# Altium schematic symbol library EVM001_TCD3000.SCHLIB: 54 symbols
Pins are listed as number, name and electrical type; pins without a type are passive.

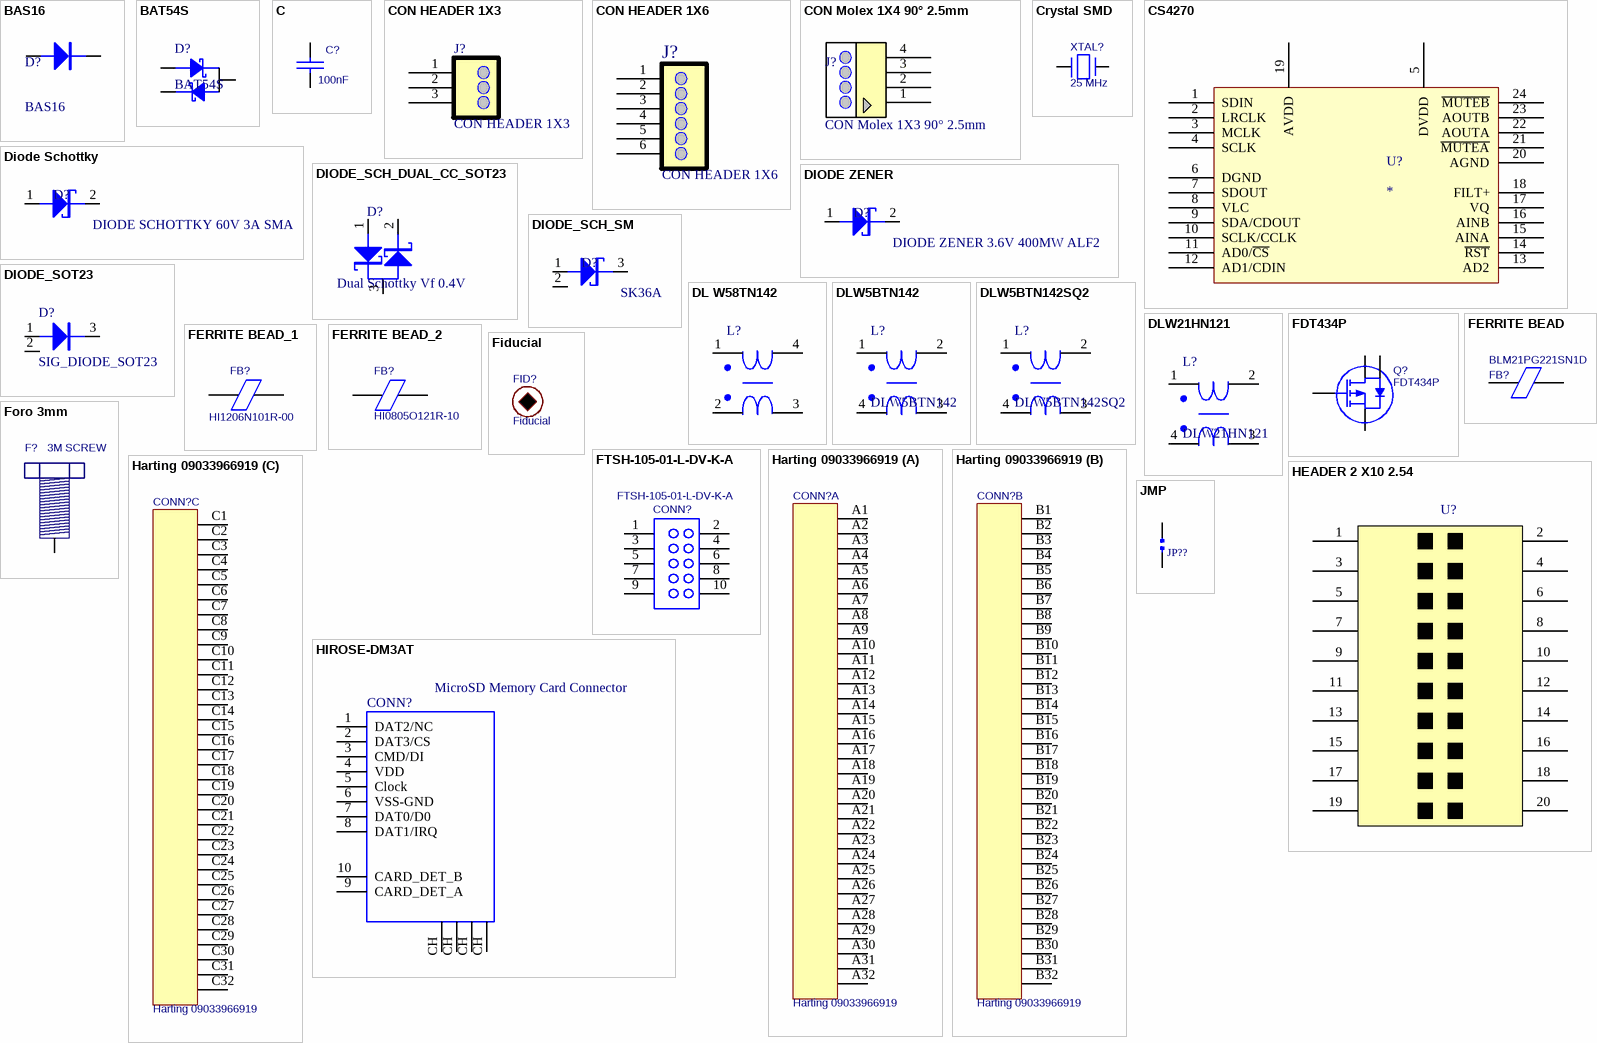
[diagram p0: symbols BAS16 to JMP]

## BAS16
designator D?
Diode
footprint SOT23
pins: 1 A, 3 K

## BAT54S
designator D?
Schottky Diodes; Manufacturer: FAIRCHILD
footprint SOT23
pins: 1, 2, 3

## C
designator C?, comment 100nF
Capacitor SMD Ceramic X7R
footprint 0402_C (Capacità SMD 0402)
footprint 0603_c (Capacità SMD 0603)
footprint 0805_C (Capacità SMD 0805)
pins: 1, 2

## CON HEADER 1X3
designator J?
Header 1 x 3
footprint HDR1X3
pins: 1, 2, 3

## CON HEADER 1X6
designator J?
Header 1 x 6
footprint HDR1X6
pins: 1, 2, 3, 4, 5, 6
2 alternate drawings of the same symbol

## CON Molex 1X4 90° 2.5mm
designator J?, comment CON Molex 1X3 90° 2.5mm
Part Field 1: Molex Inc 0894000420
footprint Molex Spox 4pin (CONN HEADER 4POS 2MM VERT T/H)
pins: 1, 2, 3, 4

## Crystal SMD
designator XTAL?, comment 25 MHz
25MHz +/-30ppm 18pF; Manufacturer: TXC; Manufacturer Code: 7A-25.000MAAJ-T
footprint TXC 7A SERIES
pins: 1, 2

## CS4270
designator U?
CODEC; Part Field 1: DK CS4270-CZZR-ND
footprint TSOP65P640-24AN (TSOP, 24-Leads, Body 7.8x4.4mm, Pitch 0.65mm, IPC Medium Density)
pins: 1 SDIN, 2 LRCLK, 3 MCLK, 4 SCLK, 5 DVDD (power), 6 DGND (power), 7 SDOUT, 8 VLC, 9 SDA/CDOUT, 10 SCLK/CCLK, 11 AD0/~{CS}, 12 AD1/CDIN, 13 AD2, 14 ~{RST}, 15 AINA, 16 AINB, 17 VQ, 18 FILT+, 19 AVDD (power), 20 AGND (power), 21 ~{MUTEA}, 22 AOUTA, 23 AOUTB, 24 ~{MUTEB}

## Diode Schottky
designator D?, comment DIODE SCHOTTKY 60V 3A SMA
Part field 1: Micro Commercial Co SK36A-TP
footprint DIODE_SMA
pins: 1, 2

## DIODE ZENER
designator D?, comment DIODE ZENER 3.6V 400MW ALF2
Part field 1: NXP Semiconductors
footprint DIODE_SMA
pins: 1, 2

## DIODE_SCH_DUAL_CC_SOT23
designator D?, comment Dual Schottky Vf 0.4V
BAT54S; Part field 1: Fairchild Semiconductor  BAT54S
footprint SOT23-3N
pins: 1, 2 NC, 3

## DIODE_SCH_SM
designator D?, comment SK36A
Diode Schottky
footprint SOT23-3N
pins: 1, 2 NC, 3

## DIODE_SOT23
designator D?, comment SIG_DIODE_SOT23
Part Field 1: Zetex BAS21
footprint SOT23CC
footprint SOT23
pins: 1, 2 NC, 3
2 alternate drawings of the same symbol

## DL W58TN142
designator L?
TRASF
footprint CM3322
footprint WE-SL2 (SMD Common Mode Line Filter)
pins: 1, 2, 3, 4

## DLW5BTN142
designator L?
CHOKE COMMON MODE 1400 OHM 2020
footprint CM3322
footprint WE-SL2 (SMD Common Mode Line Filter)
pins: 1, 2, 3, 4

## DLW5BTN142SQ2
designator L?
CHOKE COMMON MODE 1400 OHM 2020
footprint CM3322
footprint WE-SL2 (SMD Common Mode Line Filter)
pins: 1, 2, 3, 4

## DLW21HN121
designator L?
CHOKE COMMON MODE 120 OHM 0805
footprint CM3322
footprint WE-SL2 (SMD Common Mode Line Filter)
pins: 1, 2, 3, 4

## FDT434P
designator Q?
P-Channel 2.5V Specified PowerTrench MOSFET; Manufacturer: Fairchild
footprint SOT-223
pins: 1 G, 2 D, 3 S, 4 D

## FERRITE BEAD
designator FB?, comment BLM21PG221SN1D
Ferrite Bead 3A 220Ohm; Manufacturer: Murata
footprint 0805_L (Ferrite SMD 0805)
pins: 1, 2

## FERRITE BEAD_1
designator FB?, comment HI1206N101R-00
Ferrite Bead 3A 100Ohm; Manufacturer: Laird-Signal Integrity Products
footprint 1206_l
pins: 1, 2

## FERRITE BEAD_2
designator FB?, comment HI0805O121R-10
Ferrite Bead 3.5A 120Ohm; Manufacturer: Laird-Signal Integrity Products
footprint 1206_l
footprint 0805_L (Ferrite SMD 0805)
pins: 1, 2

## Fiducial
designator FID?  (no BOM)
footprint FIDUCIAL 3MM R

## Foro 3mm
designator F?, comment 3M SCREW  (no BOM)
footprint SCREW M3 (Vite 3mm)
pins: 1

## FTSH-105-01-L-DV-K-A
designator CONN?
.050'' Micro Terminal Strip; Manufacturer: Samtec
footprint FTSH-105-01-L-DV-K-A (SMD Micro Header 1.27mm Pitch)
pins: 1, 2, 3, 4, 5, 6, 7, 8, 9, 10

## Harting 09033966919
designator CONN?
VME Male 96 Pin
footprint Harting 09033966919 (VME male Connecotr)
part A pins: A1, A2, A3, A4, A5, A6, A7, A8, A9, A10, A11, A12, A13, A14, A15, A16, A17, A18, A19, A20, A21, A22, A23, A24, A25, A26, A27, A28, A29, A30, A31, A32
part B pins: B1, B2, B3, B4, B5, B6, B7, B8, B9, B10, B11, B12, B13, B14, B15, B16, B17, B18, B19, B20, B21, B22, B23, B24, B25, B26, B27, B28, B29, B30, B31, B32
part C pins: C1, C2, C3, C4, C5, C6, C7, C8, C9, C10, C11, C12, C13, C14, C15, C16, C17, C18, C19, C20, C21, C22, C23, C24, C25, C26, C27, C28, C29, C30, C31, C32

## HEADER 2 X10 2.54
designator U?  (value not drawn)
HEADER 2X10
footprint IDC2.54-V64C 5 X 81.28 (Connector; IDC, PCB Transition - 2 Rows, Thru-Hole; 64 Position; Vertical; Pitch 2.54 mm; Body 86.58 x 6.1 x 7.45 mm (LxWxH), Kinked Contacts)
pins: 1, 2, 3, 4, 5, 6, 7, 8, 9, 10, 11, 12, 13, 14, 15, 16, 17, 18, 19, 20

## HIROSE-DM3AT
designator CONN?, comment MicroSD Memory Card Connector
CONN MICRO SD R/A PUSH-PUSH SMD; Manufacturer: Hirose Electric Co Ltd; Manufacturer Code: DM3AT-SF-PEJM5
footprint DM3AT (Footprint not found)
pins: 1 DAT2/NC, 2 DAT3/CS, 3 CMD/DI, 4 VDD, 5 Clock, 6 VSS-GND, 7 DAT0/D0, 8 DAT1/IRQ, 9 CARD_DET_A, 10 CARD_DET_B, CH, CH, CH, CH

## JMP
designator JP??, comment JUMP 0.1"  (value not drawn)
footprint HDR1X2
footprint HDR1X2
pins: 1, 2

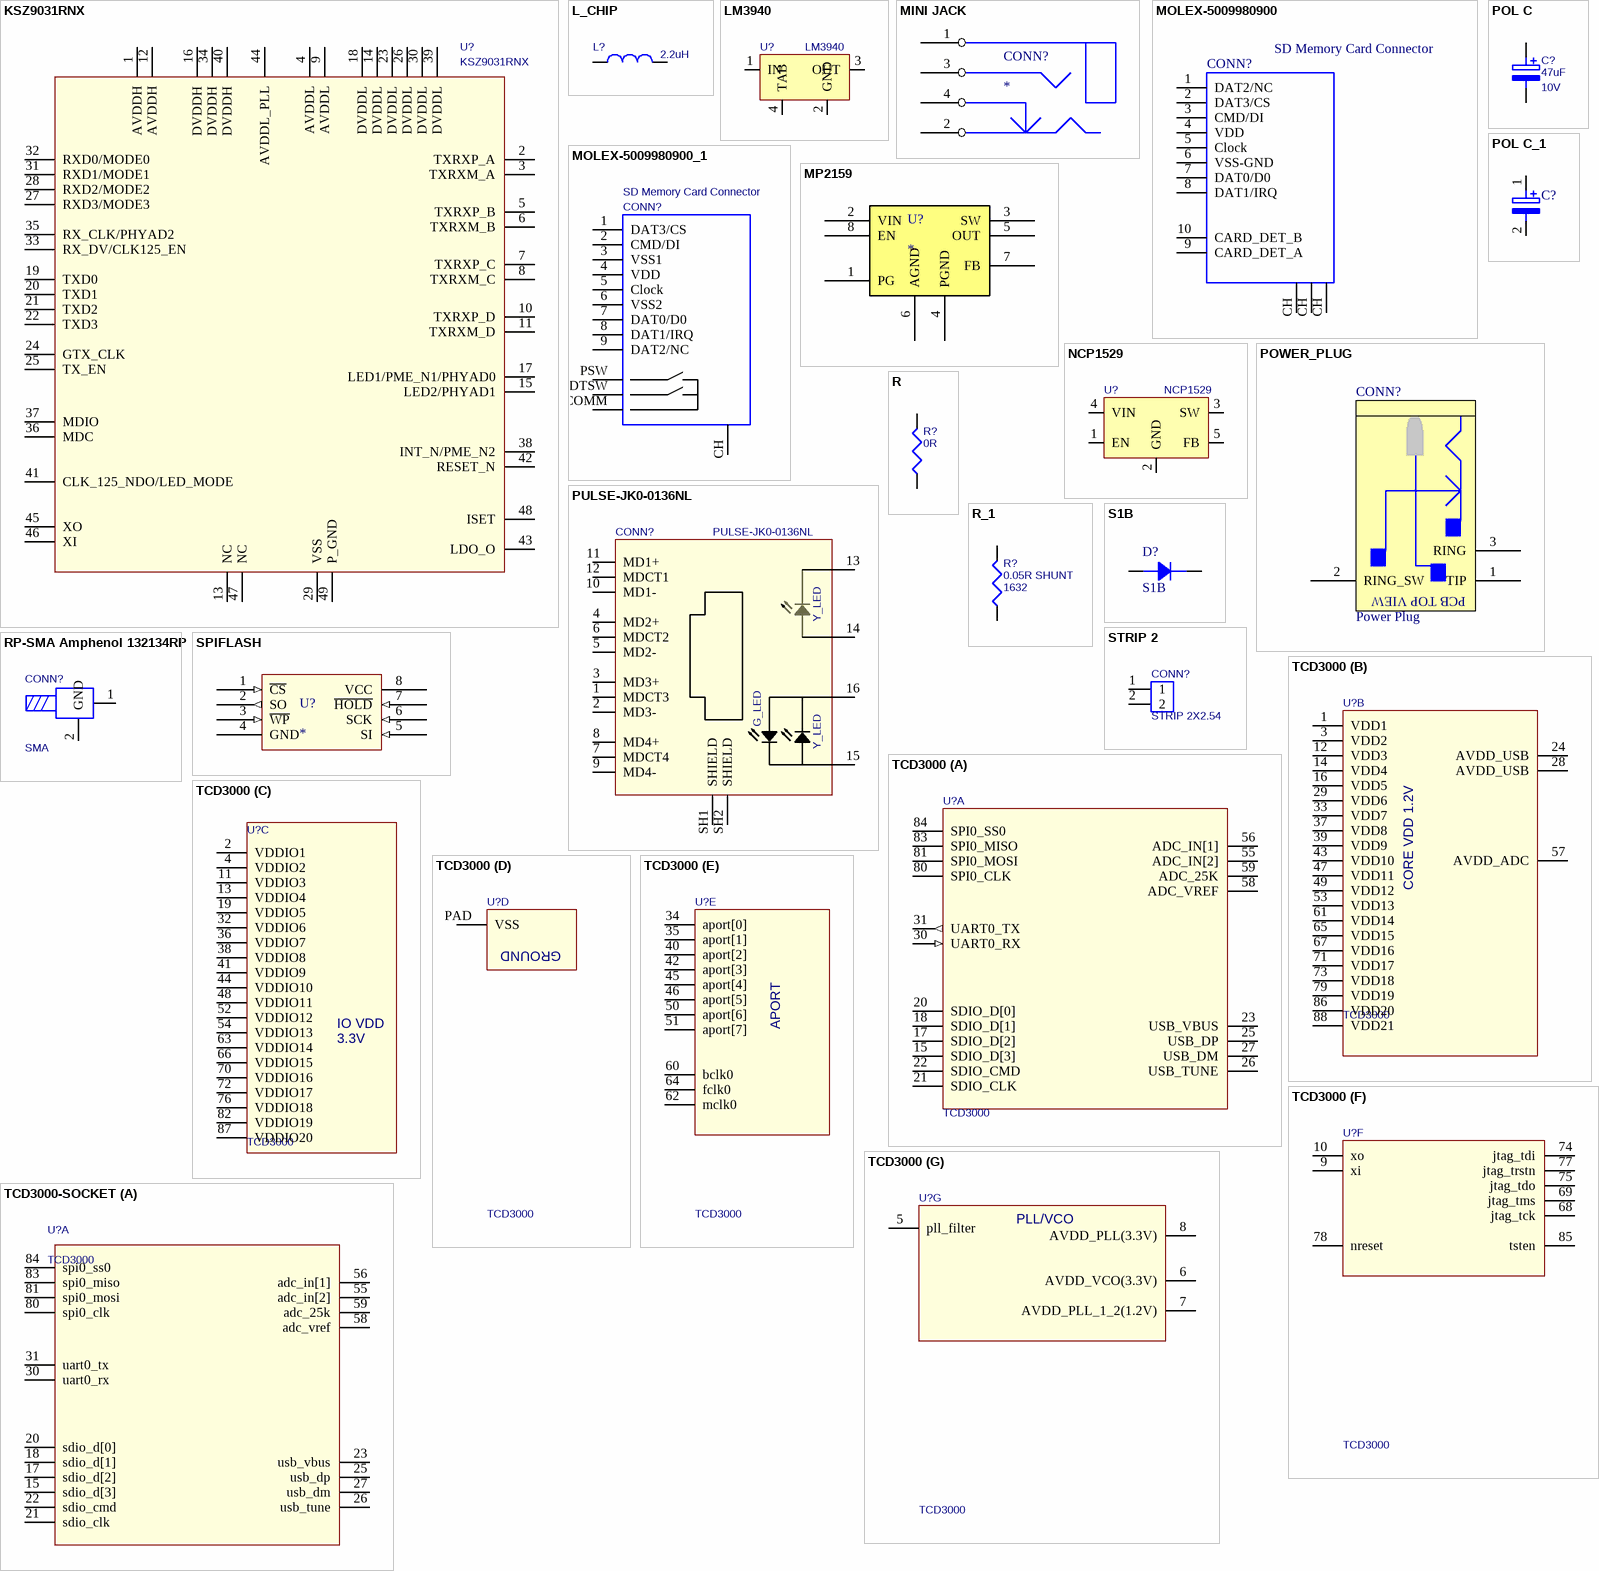
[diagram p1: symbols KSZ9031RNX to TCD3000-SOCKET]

## KSZ9031RNX
designator U?
Gigabit Ethernet Transceiver with RGMII Support; Manufacturer: Micrel; Manufacturer Code: 48-QFN
footprint MICREL-QFN-48
pins: 1 AVDDH, 2 TXRXP_A, 3 TXRXM_A, 4 AVDDL, 5 TXRXP_B, 6 TXRXM_B, 7 TXRXP_C, 8 TXRXM_C, 9 AVDDL, 10 TXRXP_D, 11 TXRXM_D, 12 AVDDH, 13 NC, 14 DVDDL, 15 LED2/PHYAD1, 16 DVDDH, 17 LED1/PME_N1/PHYAD0, 18 DVDDL, 19 TXD0, 20 TXD1, 21 TXD2, 22 TXD3, 23 DVDDL, 24 GTX_CLK, 25 TX_EN, 26 DVDDL, 27 RXD3/MODE3, 28 RXD2/MODE2, 29 VSS, 30 DVDDL, 31 RXD1/MODE1, 32 RXD0/MODE0, 33 RX_DV/CLK125_EN, 34 DVDDH, 35 RX_CLK/PHYAD2, 36 MDC, 37 MDIO, 38 INT_N/PME_N2, 39 DVDDL, 40 DVDDH, 41 CLK_125_NDO/LED_MODE, 42 RESET_N, 43 LDO_O, 44 AVDDL_PLL, 45 XO, 46 XI, 47 NC, 48 ISET, 49 P_GND

## L_CHIP
designator L?, comment 2.2uH
Chip Inductor SMD, 2.2uH, 1.3A, 80mOhm; Manufacturer: Murata; Manufacturer Code: LQM2HPN2R2MG0L
footprint Taiyo Yuden Power-Ind NR Series
footprint 1208_L
pins: 1, 2

## LM3940
designator U?
1A Low Dropout Regulator for 5V to 3.3V Conversion; Manufacturer: Texas Instruments; Manufacturer Code: LM3940IMP-3.3
footprint SOT-223
pins: 1 IN, 2 GND, 3 OUT, 4 TAB

## MINI JACK
designator CONN?
footprint SJ1_3514_SMT
pins: 1, 2, 3, 4

## MOLEX-5009980900
designator CONN?, comment SD Memory Card Connector
SD Memory Card Connector, 2.50mm Pitch, Shielded, Top Mount, Push-Push Ejector; Manufacturer: Molex; Manufacturer Code: 5009980900
footprint MOLEX - 5009980900 (2.50mm (.098") Pitch SD Memory Card Connector, Shielded, Top Mount, Push-Push Ejector)
pins: 1 DAT2/NC, 2 DAT3/CS, 3 CMD/DI, 4 VDD, 5 Clock, 6 VSS-GND, 7 DAT0/D0, 8 DAT1/IRQ, 9 CARD_DET_A, 10 CARD_DET_B, CH, CH, CH

## MOLEX-5009980900_1
designator CONN?, comment SD Memory Card Connector
SD Memory Card Connector, 2.50mm Pitch, Shielded, Top Mount, Push-Push Ejector; Manufacturer: Molex; Manufacturer Code: 5009980900
footprint MOLEX - 5009980900 (2.50mm (.098") Pitch SD Memory Card Connector, Shielded, Top Mount, Push-Push Ejector)
pins: 1 DAT3/CS, 2 CMD/DI, 3 VSS1, 4 VDD, 5 Clock, 6 VSS2, 7 DAT0/D0, 8 DAT1/IRQ, 9 DAT2/NC, CH, COMM, DTSW, PSW

## MP2159
designator U?
Voltage Regulators - Switching Regulators 1A, 6V, 1.5MHz COT Sync Step Dwn Swtchr; Part field 1: Mouser  946-MP2159GJP
pins: 1 PG, 2 VIN (power), 3 SW, 4 PGND (power), 5 OUT, 6 AGND (power), 7 FB, 8 EN

## NCP1529
designator U?
1.7MHz, 1A, High Efficiency, Low Ripple, Adjustable Output Voltage Step-down Converter; Manufacturer: On Semiconductor
footprint TSOP-5
pins: 1 EN, 2 GND, 3 SW, 4 VIN, 5 FB

## POL C
designator C?, comment 47uF  VOLT: 10V
Pol Capacitor SMD
footprint C TANT CASE A (Tantalum Capacitor Case A)
footprint C TANT CASE B (Tantalum Capacitor Case B)
footprint C TANT CASE C (Tantalum Capacitor Case C)
footprint C TANT CASE D (Tantalum Capacitor Case D)
pins: 1+, 2

## POL C_1
designator C?
Pol Capacitor SMD
footprint ALU_SMD_F
pins: 1 (power), 2 (power)

## POWER_PLUG
designator CONN?, comment Power Plug
POWER IN
footprint CON_DC_GN000111 (DC connector)
pins: 1 TIP, 2 RING_SW, 3 RING

## PULSE-JK0-0136NL
designator CONN?
100/1000 Ethernet RJ45 Integrated Mag Led; Manufacturer: Pulse
footprint PULSE-JK0-0136NL
pins: 1 MDCT3, 2 MD3-, 3 MD3+, 4 MD2+, 5 MD2-, 6 MDCT2, 7 MDCT4, 8 MD4+, 9 MD4-, 10 MD1-, 11 MD1+, 12 MDCT1, 13, 14, 15, 16, SH1 SHIELD, SH2 SHIELD

## R
designator R?, comment 0R
Resistor SMD; TOLL: 1%
footprint 0402_R (Resistenza SMD 0402)
footprint 0603_R (Resistenza SMD 0603)
footprint 0805_R (Resistenza SMD 0805)
pins: 1, 2

## R_1
designator R?, comment 0.05R SHUNT  CASE: 1632
Shunt Resistor SMD Ohmite MCS Series; Manufacturer Code: MCS1632R050FER; WATT: 1; TOLL: 1%
footprint 0402_R (Resistenza SMD 0402)
footprint 0603_R (Resistenza SMD 0603)
footprint 0805_R (Resistenza SMD 0805)
footprint 1206_R (Chip Resistor 120x60mils)
pins: 1, 2

## RP-SMA Amphenol 132134RP
designator CONN?, comment SMA
CONN SMA JACK STR 50 OHM PCB; Manufacturer: TE Connectivity; Manufacturer Code: 5-1814832-1
footprint RP-SMA Amphenol 132134RP
pins: 1, 2 GND

## S1B
designator D?
1.0A SURFACE MOUNT GLASS PASSIVATED RECTIFIER
footprint SMA (SMA Diodes Case)
pins: A, K

## SPIFLASH
designator U?
IC FLASH 16MBIT 75MHZ 8SO; Part field 1: Micron M25P16-VMN6TP
footprint SOIC150-8N
pins: 1 ~{CS} (in), 2 SO (out), 3 ~{WP} (in), 4 GND (power), 5 SI (in), 6 SCK (in), 7 ~{HOLD} (in), 8 VCC (power)

## STRIP 2
designator CONN?, comment STRIP 2X2.54
STRIP CONNECTOR
footprint STRIP 2
pins: 1, 2

## TCD3000
designator U?
footprint TCD-3040 SOCKET
part A pins: 15 SDIO_D[3], 17 SDIO_D[2], 18 SDIO_D[1], 20 SDIO_D[0], 21 SDIO_CLK, 22 SDIO_CMD, 23 USB_VBUS, 25 USB_DP, 26 USB_TUNE, 27 USB_DM, 30 UART0_RX (in), 31 UART0_TX (out), 55 ADC_IN[2], 56 ADC_IN[1], 58 ADC_VREF, 59 ADC_25K, 80 SPI0_CLK, 81 SPI0_MOSI, 83 SPI0_MISO, 84 SPI0_SS0
part B pins: 1 VDD1, 3 VDD2, 12 VDD3, 14 VDD4, 16 VDD5, 24 AVDD_USB, 28 AVDD_USB, 29 VDD6, 33 VDD7, 37 VDD8, 39 VDD9, 43 VDD10, 47 VDD11, 49 VDD12, 53 VDD13, 57 AVDD_ADC, 61 VDD14, 65 VDD15, 67 VDD16, 71 VDD17, 73 VDD18, 79 VDD19, 86 VDD20, 88 VDD21
part C pins: 2 VDDIO1, 4 VDDIO2, 11 VDDIO3, 13 VDDIO4, 19 VDDIO5, 32 VDDIO6, 36 VDDIO7, 38 VDDIO8, 41 VDDIO9, 44 VDDIO10, 48 VDDIO11, 52 VDDIO12, 54 VDDIO13, 63 VDDIO14, 66 VDDIO15, 70 VDDIO16, 72 VDDIO17, 76 VDDIO18, 82 VDDIO19, 87 VDDIO20
part D pins: PAD VSS
part E pins: 34 aport[0], 35 aport[1], 40 aport[2], 42 aport[3], 45 aport[4], 46 aport[5], 50 aport[6], 51 aport[7], 60 bclk0, 62 mclk0, 64 fclk0
part F pins: 9 xi, 10 xo, 68 jtag_tck, 69 jtag_tms, 74 jtag_tdi, 75 jtag_tdo, 77 jtag_trstn, 78 nreset, 85 tsten
part G pins: 5 pll_filter, 6 AVDD_VCO(3.3V), 7 AVDD_PLL_1_2(1.2V), 8 AVDD_PLL(3.3V)

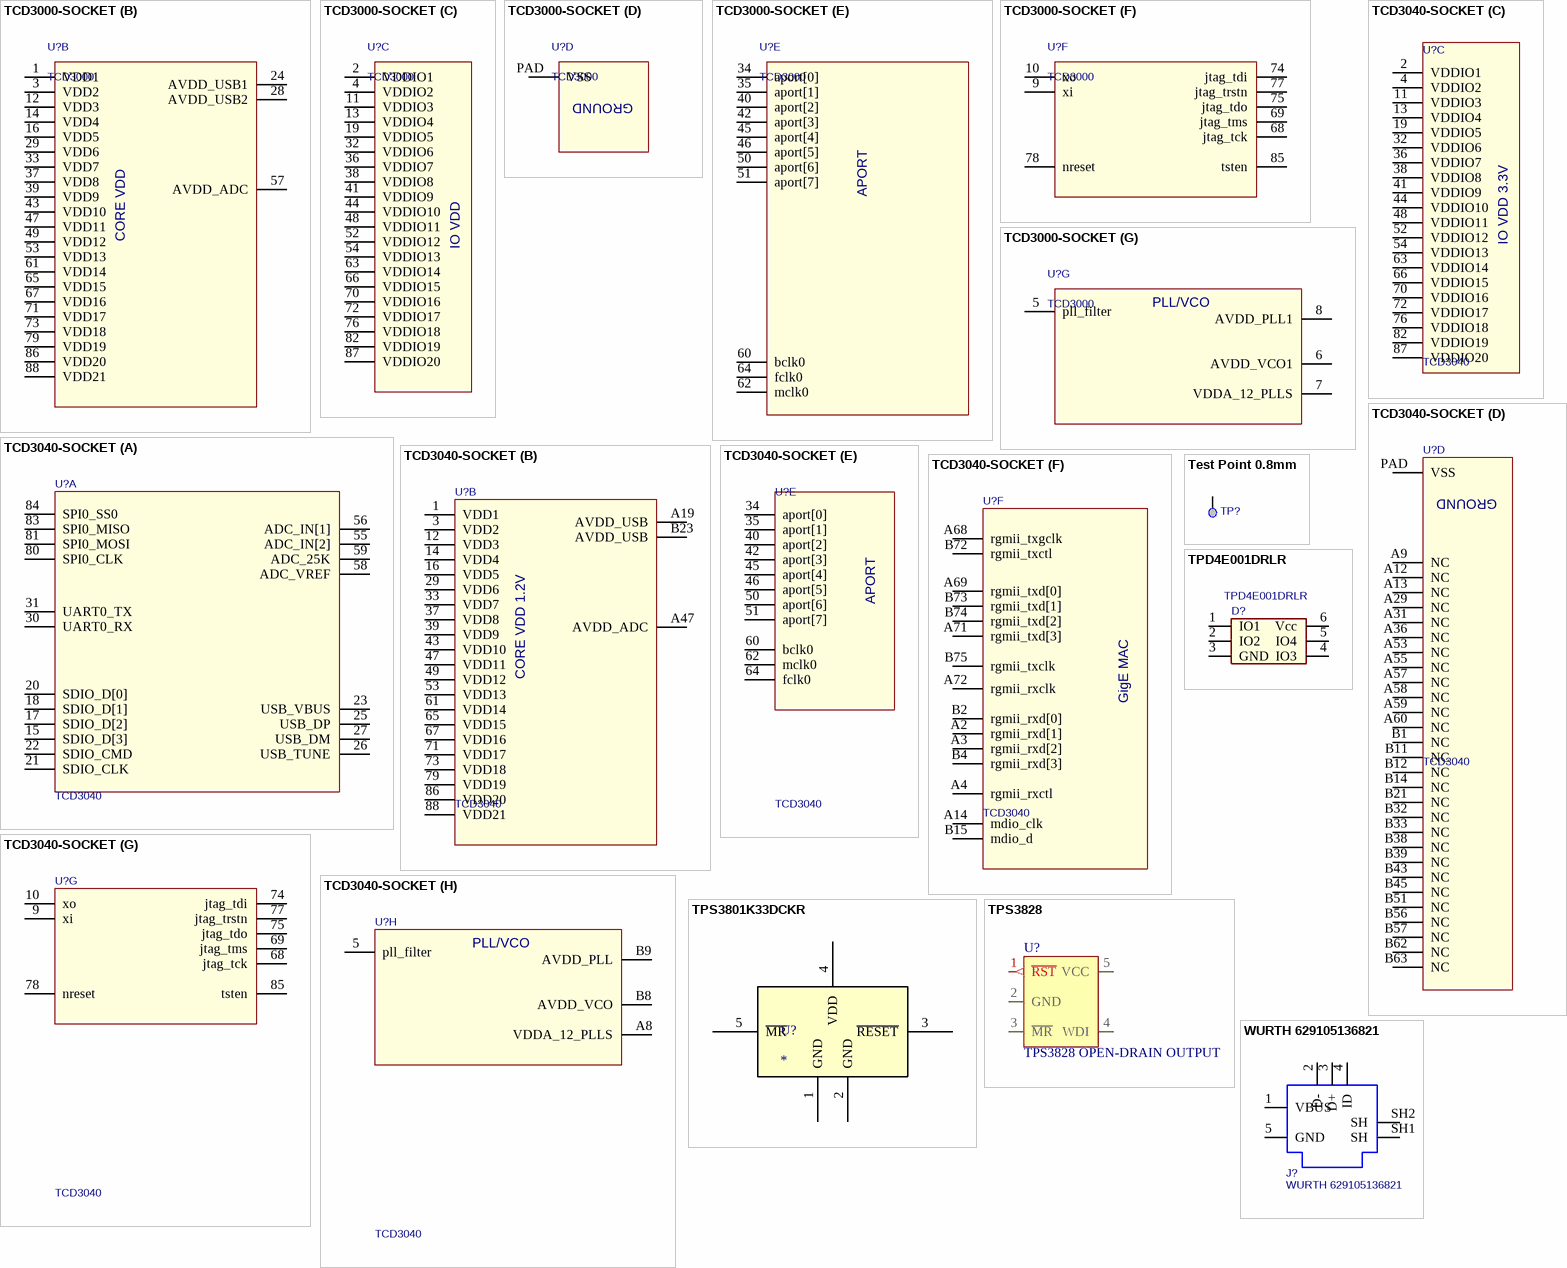
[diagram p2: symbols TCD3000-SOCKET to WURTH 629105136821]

## TCD3000-SOCKET
designator U?, comment TCD3000
footprint TCD-3000 SOCKET
part A pins: 15 sdio_d[3], 17 sdio_d[2], 18 sdio_d[1], 20 sdio_d[0], 21 sdio_clk, 22 sdio_cmd, 23 usb_vbus, 25 usb_dp, 26 usb_tune, 27 usb_dm, 30 uart0_rx, 31 uart0_tx, 55 adc_in[2], 56 adc_in[1], 58 adc_vref, 59 adc_25k, 80 spi0_clk, 81 spi0_mosi, 83 spi0_miso, 84 spi0_ss0
part B pins: 1 VDD1, 3 VDD2, 12 VDD3, 14 VDD4, 16 VDD5, 24 AVDD_USB1, 28 AVDD_USB2, 29 VDD6, 33 VDD7, 37 VDD8, 39 VDD9, 43 VDD10, 47 VDD11, 49 VDD12, 53 VDD13, 57 AVDD_ADC, 61 VDD14, 65 VDD15, 67 VDD16, 71 VDD17, 73 VDD18, 79 VDD19, 86 VDD20, 88 VDD21
part C pins: 2 VDDIO1, 4 VDDIO2, 11 VDDIO3, 13 VDDIO4, 19 VDDIO5, 32 VDDIO6, 36 VDDIO7, 38 VDDIO8, 41 VDDIO9, 44 VDDIO10, 48 VDDIO11, 52 VDDIO12, 54 VDDIO13, 63 VDDIO14, 66 VDDIO15, 70 VDDIO16, 72 VDDIO17, 76 VDDIO18, 82 VDDIO19, 87 VDDIO20
part D pins: PAD VSS
part E pins: 34 aport[0], 35 aport[1], 40 aport[2], 42 aport[3], 45 aport[4], 46 aport[5], 50 aport[6], 51 aport[7], 60 bclk0, 62 mclk0, 64 fclk0
part F pins: 9 xi, 10 xo, 68 jtag_tck, 69 jtag_tms, 74 jtag_tdi, 75 jtag_tdo, 77 jtag_trstn, 78 nreset, 85 tsten
part G pins: 5 pll_filter, 6 AVDD_VCO1, 7 VDDA_12_PLLS, 8 AVDD_PLL1

## TCD3040-SOCKET
designator U?, comment TCD3040
footprint TCD-3040 SOCKET
part A pins: 15 SDIO_D[3], 17 SDIO_D[2], 18 SDIO_D[1], 20 SDIO_D[0], 21 SDIO_CLK, 22 SDIO_CMD, 23 USB_VBUS, 25 USB_DP, 26 USB_TUNE, 27 USB_DM, 30 UART0_RX, 31 UART0_TX, 55 ADC_IN[2], 56 ADC_IN[1], 58 ADC_VREF, 59 ADC_25K, 80 SPI0_CLK, 81 SPI0_MOSI, 83 SPI0_MISO, 84 SPI0_SS0
part B pins: 1 VDD1, 3 VDD2, 12 VDD3, 14 VDD4, 16 VDD5, 29 VDD6, 33 VDD7, 37 VDD8, 39 VDD9, 43 VDD10, 47 VDD11, 49 VDD12, 53 VDD13, 61 VDD14, 65 VDD15, 67 VDD16, 71 VDD17, 73 VDD18, 79 VDD19, 86 VDD20, 88 VDD21, A19 AVDD_USB, A47 AVDD_ADC, B23 AVDD_USB
part C pins: 2 VDDIO1, 4 VDDIO2, 11 VDDIO3, 13 VDDIO4, 19 VDDIO5, 32 VDDIO6, 36 VDDIO7, 38 VDDIO8, 41 VDDIO9, 44 VDDIO10, 48 VDDIO11, 52 VDDIO12, 54 VDDIO13, 63 VDDIO14, 66 VDDIO15, 70 VDDIO16, 72 VDDIO17, 76 VDDIO18, 82 VDDIO19, 87 VDDIO20
part D pins: A9 NC, A12 NC, A13 NC, A29 NC, A31 NC, A36 NC, A53 NC, A55 NC, A57 NC, A58 NC, A59 NC, A60 NC, B1 NC, B11 NC, B12 NC, B14 NC, B21 NC, B32 NC, B33 NC, B38 NC, B39 NC, B43 NC, B45 NC, B51 NC, B56 NC, B57 NC, B62 NC, B63 NC, PAD VSS
part E pins: 34 aport[0], 35 aport[1], 40 aport[2], 42 aport[3], 45 aport[4], 46 aport[5], 50 aport[6], 51 aport[7], 60 bclk0, 62 mclk0, 64 fclk0
part F pins: A2 rgmii_rxd[1], A3 rgmii_rxd[2], A4 rgmii_rxctl, A14 mdio_clk, A68 rgmii_txgclk, A69 rgmii_txd[0], A71 rgmii_txd[3], A72 rgmii_rxclk, B2 rgmii_rxd[0], B4 rgmii_rxd[3], B15 mdio_d, B72 rgmii_txctl, B73 rgmii_txd[1], B74 rgmii_txd[2], B75 rgmii_txclk
part G pins: 9 xi, 10 xo, 68 jtag_tck, 69 jtag_tms, 74 jtag_tdi, 75 jtag_tdo, 77 jtag_trstn, 78 nreset, 85 tsten
part H pins: 5 pll_filter, A8 VDDA_12_PLLS, B8 AVDD_VCO, B9 AVDD_PLL

## Test Point 0.8mm
designator TP?, comment TP  (value not drawn)  (no BOM)
Test Point 0.8mm
footprint Test Point 0.8mm B (Test Point 0.8mm Bottom Layer)
footprint Test Point 0.8mm T (Test Point 0.8mm Top Layer)
footprint Test Point 0.8 PTH (Test Point 0.8mm PTH)
pins: 1

## TPD4E001DRLR
designator D?
Low-Capacitance 4-Channel +/-15-kV ESD Protection Array for High-Speed Data Interfaces (1.5pF)); Manufacturer: Texas Instruments
footprint SOT6 (DRL)
pins: 1 IO1, 2 IO2, 3 GND, 4 IO3, 5 IO4, 6 Vcc

## TPS3801K33DCKR
designator U?
Part field 1: TI TPS3801K33DCKR
pins: 1 GND, 2 GND, 3 ~{RESET}, 4 VDD, 5 ~{MR}

## TPS3828
designator U?, comment TPS3828 OPEN-DRAIN OUTPUT
IC 2.93V SUPPLY MONITOR SOT23-5 ACTIVE LOW OPEN-DRAIN OUTPUT; Part field 1: TI TPS3828-33DBVR
footprint SOT23-5AN (SOT23, 5-Leads, Body 2.9x1.6mm, Pitch 0.95mm, Lead Span 2.8mm, IPC Medium Density)
pins: 1 ~{RST} (out), 2 GND (power), 3 ~{MR}, 4 WDI, 5 VCC (power)

## WURTH 629105136821
designator J?
micro_USB, 5 pins, SMD
footprint Wurth - 629105136821
pins: 1 VBUS, 2 D-, 3 D+, 4 ID, 5 GND, SH1 SH, SH2 SH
